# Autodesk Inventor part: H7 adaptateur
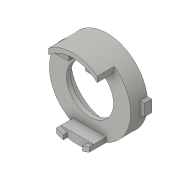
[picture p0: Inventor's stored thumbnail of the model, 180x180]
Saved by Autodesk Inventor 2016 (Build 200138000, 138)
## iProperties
Created: 2018-04
Part Number: H7 adaptateur
Material: Generic
Document SubType Name: Modeling
Designer: Justin
Density: 1 g/cm^3
Appearance: Default
Author: Justin
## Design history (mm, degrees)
sketch "Sketch1"
  geometry: C1 r 19 at (0, 0); C2 r 17 at (0, 0); 1 further point
  constraints: 2 centre point, 2 coincident
  dimensions: "d0" = 38 diameter of C1; "d1" = 34 diameter of C2
extrude "Extrusion1" new body sketch "Sketch1" distance "d2" = 6; taper "d3" = 0 deg
sketch "Sketch2"
  geometry: L1 (18.591, 3.923)-(20.63, 3.923); L2 (18.792, -2.802)-(20.812, -2.802); L3 (-18.791, 2.808)-(-20.811, 2.808); L4 (-18.791, -2.808)-(-20.811, -2.808); A1 r 19 centre (0, 0) between (18.591, 3.923) and (18.792, -2.802) reference; A2 r 21 centre (0, 0) between (-20.811, 2.808) and (-20.811, -2.808); A3 r 21 centre (0, 0) between (20.812, -2.802) and (20.63, 3.923)
  constraints: 8 end point, 8 point on circle, 2 centre point, 2 parallel, 1 coincident, 1 horizontal
extrude "Extrusion2" join sketch "Sketch2" distance "d5" = 3.5; taper "d6" = 0 deg
sketch "Sketch3"
  geometry: C1 r 19 at (0, 0) reference; C2 r 19 at (0, 0); C3 r 11 at (0, 0)
  constraints: 2 centre point, 2 coincident, 1 concentric
  dimensions: "d7" = 22 diameter of C3
extrude "Extrusion3" join sketch "Sketch3" distance "d8" = 2; taper "d9" = 0 deg
sketch "Sketch4"
  geometry: L1 (-7.679, -15.167)-(-7.679, -17.379); L2 (-7.679, -15.167)-(-5.467, -15.167); L3 (7.679, -17.379)-(7.679, -15.167); L4 (7.679, -17.379)-(9.892, -17.379); L5 (-7.679, -15.167)-(7.679, -15.167); L6 (7.679, -17.379)-(-7.679, -17.379); L7 (7.679, -17.379)-(7.679, -14.379); L8 (7.679, -14.379)-(-7.679, -14.379); L9 (-7.679, -14.379)-(-7.679, -17.379); L10 (7.679, -17.379)-(7.679, -14.379); L11 (-7.679, -14.379)-(-7.679, -17.379); L12 (11.348, 12.658)-(-11.348, 12.658); L13 (11.348, 12.658)-(34.043, 12.658); L14 (11.348, 12.658)-(11.348, 15.239); L15 (11.348, 12.658)-(13.929, 12.658); L16 (-11.348, 12.658)-(-11.348, 15.239); L17 (-11.348, 12.658)-(-8.767, 12.658); L18 (11.348, 12.658)-(3.964, 12.658); L19 (3.964, 15.812)-(3.964, 12.658); L20 (-3.951, 15.815)-(-3.951, 12.658); L21 (-11.348, 12.658)-(-3.951, 12.658); L22 (3.964, 12.658)-(3.964, 16.531); L23 (3.964, 12.658)-(7.838, 12.658); L24 (-3.951, 16.534)-(-3.951, 12.658); L25 (7.679, -14.379)-(-7.679, -14.379); A1 r 19 centre (0, 0) between (7.679, -17.379) and (-18.591, 3.923) reference; A2 r 19 centre (0, 0) between (-7.679, -17.379) and (7.679, -17.379); A3 r 17 centre (0, 0) between (11.348, 12.658) and (-11.348, 12.658) reference; A4 r 16.301 centre (0, 0) between (-7.679, -14.379) and (3.964, 15.812); A5 r 19 centre (0, 0) between (18.791, 2.808) and (-18.591, 3.923) reference; A6 r 17 centre (0, 0) between (3.964, 16.531) and (-3.951, 16.534); A7 r 16.301 centre (0, 0) between (-7.679, -14.379) and (-5.975, -15.167); A8 r 16.301 centre (0, 0) between (5.975, -15.167) and (7.679, -14.379)
  constraints: 50 end point, 20 point on circle, 7 horizontal, 6 equal length, 5 centre point, 4 perpendicular, 4 point on line, 3 coincident, 2 collinear, 1 concentric, 1 parallel, 1 vertical
  dimensions: "d10" = 90 deg angle of L1 L2; "d11" = 90 deg angle of L4 L3; "d12" = 3 distance of L3.start L7.end; "d13" = 180 deg angle of L12 L13; "d14" = 90 deg angle of L15 L14; "d15" = 90 deg angle of L17 L16; "d16" = 90 deg angle of L23 L22
extrude "Extrusion4" join sketch "Sketch4" distance "d17" = 6; taper "d18" = 0 deg
sketch "Sketch5"
  geometry: L1 (11.348, 15.239)-(11.348, 12.658) reference; L2 (11.348, 15.239)-(11.348, 12.658); L3 (-11.348, 12.658)-(-11.348, 15.239) reference; L4 (-11.348, 15.239)-(-11.348, 12.658); L5 (0, -19)-(4.5, -19); L6 (4.5, -19)-(0, -19); L7 (0, -19)-(-4.5, -19); L8 (4.5, -18.459)-(4.5, -16.394); L9 (-4.5, -18.459)-(-4.5, -16.394); L10 (7.679, -17.379)-(7.679, -15.167) reference; L11 (7.679, -15.167)-(7.679, -17.379); L12 (-7.679, -15.167)-(-7.679, -17.379) reference; L13 (-7.679, -15.167)-(-7.679, -17.379); A1 r 19 centre (0, 0) between (11.348, 15.239) and (-11.348, 15.239) reference; A2 r 19 centre (0, 0) between (11.348, 15.239) and (-11.348, 15.239); A3 r 17 centre (0, 0) between (3.964, 16.531) and (-3.951, 16.534); A4 r 17 centre (0, 0) between (4.5, -16.394) and (-4.5, -16.394); A5 r 17 centre (0, 0) between (11.348, 12.658) and (-11.348, 12.658); A6 r 19 centre (0, 0) between (-18.792, -2.802) and (18.791, -2.808) reference; A7 r 19 centre (0, 0) between (4.5, -18.459) and (7.679, -17.379); A8 r 17 centre (0, 0) between (4.5, -16.394) and (7.679, -15.167); A9 r 19 centre (0, 0) between (-7.679, -17.379) and (-4.5, -18.459); A10 r 17 centre (0, 0) between (-7.679, -15.167) and (-4.5, -16.394)
  constraints: 18 end point, 18 point on circle, 8 centre point, 5 equal length, 2 tangent, 2 vertical, 1 coincident, 1 concentric, 1 horizontal, 1 point on line
  dimensions: "d19" = 4.5 distance of L5.start L5.end; "d20" = 4.5 distance of L5.start L7.end
extrude "Extrusion5" join sketch "Sketch5" distance "d21" = 2; taper "d22" = 0 deg
sketch "Sketch6"
  geometry: L1 (7.679, -15.167)-(-7.679, -15.167); A1 r 17 centre (0, 0) between (-7.679, -15.167) and (7.679, -15.167) reference
  constraints: 2 end point, 1 horizontal
extrude "Extrusion6" join sketch "Sketch6" distance "d23" = 6; taper "d24" = 0 deg
body "Solid1"
other parameters: "d4" = 42
